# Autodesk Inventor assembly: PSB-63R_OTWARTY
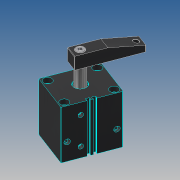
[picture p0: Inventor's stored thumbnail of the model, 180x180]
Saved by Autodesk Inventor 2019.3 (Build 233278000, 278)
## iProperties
Company: Î¢ÈíÖÐ¹ú
Created: 2013-04
Part Number: PSB-63R_OTWARTY
Material: Ogólny
Description: STEP AP203
Document SubType Name: Assembly
Designer: CADENGINEERING4
Sending System: SolidWorks 2010
Preprocessor: SwSTEP 2.0
Title: PSB-L6390-1515-00.STEP
Author: Î¢ÈíÓÃ»§
Revision Number: ÈÎºÎ
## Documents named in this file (11)
- E:\SERWER_ZAPAS\Pneumatic\PSB PNEUMATIC SWING\PSB-63\PSB-63R_OTWARTY.iam
- E:\SERWER_ZAPAS\Pneumatic\PSB PNEUMATIC SWING\PSB-63\PSB-L63-90-15-15-01.ipt
- E:\SERWER_ZAPAS\Pneumatic\PSB PNEUMATIC SWING\PSB-63\¸ÖÖé4.ipt
- E:\SERWER_ZAPAS\Pneumatic\PSB PNEUMATIC SWING\PSB-63\hex socket set screws with flat point gb_GB_FASTENER_SCREWS_HSFP M5X8-N.ipt
- E:\SERWER_ZAPAS\Pneumatic\PSB PNEUMATIC SWING\PSB-63\PSB-L63-90-15-15-04.ipt
- E:\SERWER_ZAPAS\Pneumatic\PSB PNEUMATIC SWING\PSB-63\PSB-L63-90-15-15-02.ipt
- E:\SERWER_ZAPAS\Pneumatic\PSB PNEUMATIC SWING\PSB-63\PSB-L63-90-15-15-05.ipt
- E:\SERWER_ZAPAS\Pneumatic\PSB PNEUMATIC SWING\PSB-63\hexagon socket head cap screws gb_GB_FASTENER_SCREWS_HSHCS M10X20-N.ipt
- E:\SERWER_ZAPAS\Pneumatic\PSB PNEUMATIC SWING\PSB-63\s¸Ë2.ipt
- E:\SERWER_ZAPAS\Pneumatic\PSB PNEUMATIC SWING\PSB-63\PSB-L63-90-15-15-03.ipt
- E:\SERWER_ZAPAS\Pneumatic\PSB PNEUMATIC SWING\PSB-63\4x40.ipt
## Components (14 placed, 14 different names)
1. PSB-L63-90-15-15-01_1 — Zestawiające:1, Zestawiające:2, Zestawiające:4, Kątowe:1
2. ¸ÖÖé4_2 — Zestawiające:10
3. hex socket set screws with flat point gb_GB_FASTENER_SCREWS_HSFP M5X8-N_3 — Zestawiające:10
4. hex socket set screws with flat point gb_GB_FASTENER_SCREWS_HSFP M5X8-N_4 — Zestawiające:12
5. PSB-L63-90-15-15-04_5 — Zestawiające:5, Równoległe:1, Zestawiające:6, Zestawiające:9, Zestawiające:14, Kątowe:1
6. PSB-L63-90-15-15-02_6 — Zestawiające:3, Zestawiające:4, Zestawiające:5, Zestawiające:13, Równoległe:2
7. PSB-L63-90-15-15-05_7 — Równoległe:1, Zestawiające:6, Zestawiające:8
8. ¸ÖÖé4_8 — Zestawiające:12
9. hexagon socket head cap screws gb_GB_FASTENER_SCREWS_HSHCS M10X20-N_9 — Zestawiające:1, Zestawiające:2, Zestawiające:3
10. s¸Ë2_10 — Zestawiające:7, Zestawiające:9
11. ¸ÖÖé4_11 — Zestawiające:11
12. PSB-L63-90-15-15-03_12 — Zestawiające:13, Równoległe:2, Zestawiające:14
13. 4x40_13 — Zestawiające:7, Zestawiające:8
14. hex socket set screws with flat point gb_GB_FASTENER_SCREWS_HSFP M5X8-N_14 — Zestawiające:11
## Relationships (17: Mate 14, Flush 2, Angle 1)
- Zestawiające:1 [Mate]: PSB-L63-90-15-15-01_1 ↔ hexagon socket head cap screws gb_GB_FASTENER_SCREWS_HSHCS M10X20-N_9
- Zestawiające:2 [Mate]: PSB-L63-90-15-15-01_1 ↔ hexagon socket head cap screws gb_GB_FASTENER_SCREWS_HSHCS M10X20-N_9
- Zestawiające:3 [Mate]: PSB-L63-90-15-15-02_6 ↔ hexagon socket head cap screws gb_GB_FASTENER_SCREWS_HSHCS M10X20-N_9
- Zestawiające:4 [Mate]: PSB-L63-90-15-15-01_1 ↔ PSB-L63-90-15-15-02_6
- Zestawiające:5 [Mate]: PSB-L63-90-15-15-04_5 ↔ PSB-L63-90-15-15-02_6
- Równoległe:1 [Flush]: PSB-L63-90-15-15-04_5 ↔ PSB-L63-90-15-15-05_7
- Zestawiające:6 [Mate]: PSB-L63-90-15-15-04_5 ↔ PSB-L63-90-15-15-05_7
- Zestawiające:7 [Mate]: s¸Ë2_10 ↔ 4x40_13
- Zestawiające:8 [Mate]: PSB-L63-90-15-15-05_7 ↔ 4x40_13
- Zestawiające:9 [Mate]: PSB-L63-90-15-15-04_5 ↔ s¸Ë2_10
- Zestawiające:10 [Mate]: ¸ÖÖé4_2 ↔ hex socket set screws with flat point gb_GB_FASTENER_SCREWS_HSFP M5X8-N_3
- Zestawiające:11 [Mate]: ¸ÖÖé4_11 ↔ hex socket set screws with flat point gb_GB_FASTENER_SCREWS_HSFP M5X8-N_14
- Zestawiające:12 [Mate]: hex socket set screws with flat point gb_GB_FASTENER_SCREWS_HSFP M5X8-N_4 ↔ ¸ÖÖé4_8
- Zestawiające:13 [Mate]: PSB-L63-90-15-15-02_6 ↔ PSB-L63-90-15-15-03_12
- Równoległe:2 [Flush]: PSB-L63-90-15-15-02_6 ↔ PSB-L63-90-15-15-03_12
- Zestawiające:14 [Mate]: PSB-L63-90-15-15-04_5 ↔ PSB-L63-90-15-15-03_12
- Kątowe:1 [Angle]: PSB-L63-90-15-15-01_1 ↔ PSB-L63-90-15-15-04_5
